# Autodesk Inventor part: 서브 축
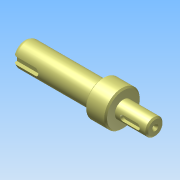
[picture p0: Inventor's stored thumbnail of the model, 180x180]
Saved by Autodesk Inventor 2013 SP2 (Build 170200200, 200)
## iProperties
Created: 2026-07
Part Number: 서브 축
Material: Generic
Document SubType Name: Modeling
Designer: aa
Density: 1 g/cm^3
Author: aa
변환 표준: STEP AP214IS
전처리기: Build: 200, Release: 2013 SP2 Update 6 - Date: Thu 07/17/2014
전송 단위: 밀리미터
불확실성: 0.01
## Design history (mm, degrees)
node "서브 축1"
node "솔리드1"
node "기준1"
